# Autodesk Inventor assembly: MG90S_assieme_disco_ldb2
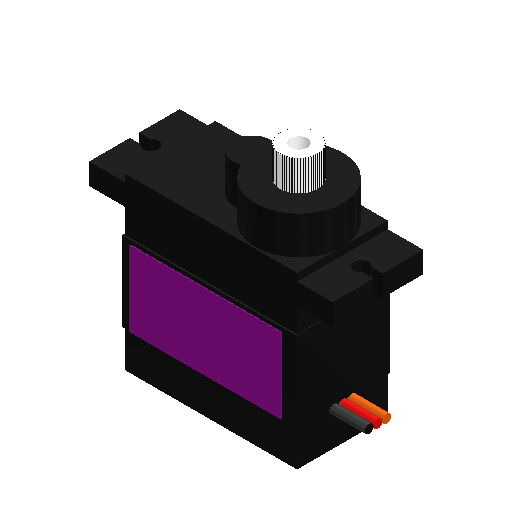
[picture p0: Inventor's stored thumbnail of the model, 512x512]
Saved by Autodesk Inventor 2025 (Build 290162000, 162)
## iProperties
Created: 2021-06
Part Number: MG90S_assieme_disco_ldb2
Document SubType Name: Assembly
Designer: Ryzen5700u
Author: Ryzen5700u
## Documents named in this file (3)
- C:\Users\Ryzen5700u\Desktop\m5\Assieme_2_robot\MG90S_assieme_disco_ldb2.iam
- C:\Users\Ryzen5700u\Desktop\m5\Assieme_2_robot\MG90_ldb.ipt
- C:\Users\Ryzen5700u\Desktop\m5\Assieme_2_robot\scritta_MG90s.ipt
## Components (3 placed, 2 different names)
1. MG90_ldb:1
2. scritta_MG90s:1
3. scritta_MG90s:2
